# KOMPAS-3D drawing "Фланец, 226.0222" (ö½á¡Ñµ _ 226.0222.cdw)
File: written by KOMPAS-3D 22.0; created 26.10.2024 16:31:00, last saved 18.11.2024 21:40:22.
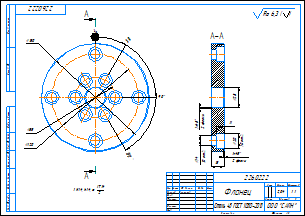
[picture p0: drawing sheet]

Sheet 1: A3, landscape

Document properties: Автор: aleksander.larionov.10@gmail.com; Знак неуказанной шероховатости: 4; Параметр неуказанной шероховатости: Ra 6,3; Масса: 2.039272; Полное имя файла: Фланец _ 226.0222.m3d

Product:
- Part/product: Фланец  | designation 226.0222
    Материал: Сталь 45 ГОСТ 1050-2013 (density 7810 kg/m3)
    Масса: 2.039272

Title block, sheet 1: Наименование: Фланец; designation: 226.0222; Материал: Сталь 45 ГОСТ 1050-2013; Масса: 2,04; Количество листов документа: 1; organisation: ООО "САЙН"; Форматы листов документа: A3; stored path: C:\Users\aleks\Desktop\Работа\226.0222\Фланец _ 226.0222.cdw; Разработал: Ларионов

Views: Вид 1, Сверху, Разрез А-А
Referenced files in C:\Users\aleks\Desktop\Работа\226.0222\: Фланец _ 226.0222.m3d
Referenced files in C:\Мои папки\Работа\Крышки, фланцы\226.0222\: Фланец _ 226.0222.m3d
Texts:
  Ra 6,3
  Ra 6,3 ( )
Dimensions and other numbers on the sheet: 150; 55; 120; 226.0222; 1; 2 фаски; 18; 20; 10 отв.; 14; 11; 28; 1 H14, h14,    IT14 2 .; 1:1; 2,04; 226.0222 Фланец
